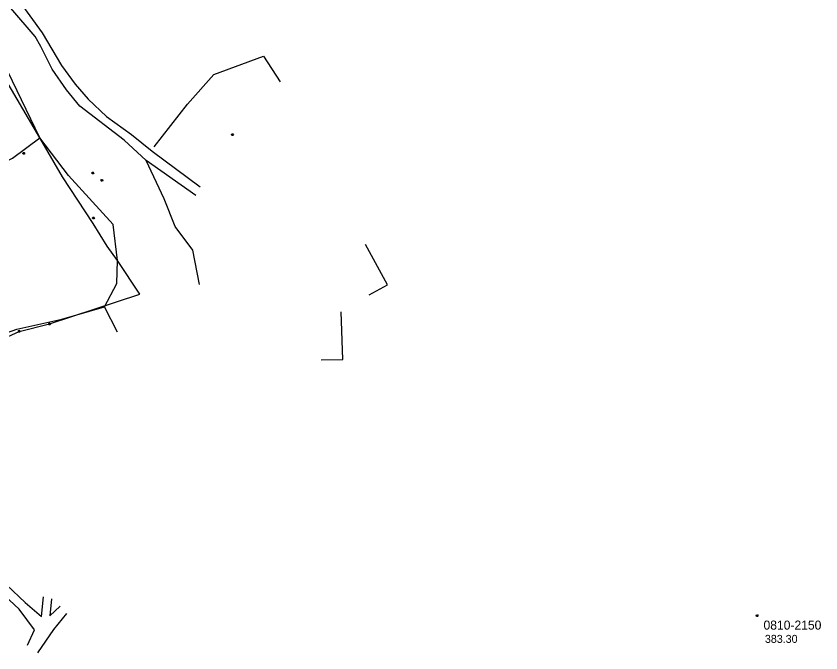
# Model space of a CAD drawing. Extents: x -664960 to -662754, y -993849 to -991145.
# Drawn here: x -663293.4 to -662991, y -993249.2 to -993009.9 of the extents above; entities that cross this region are included whole.
import ezdxf

# ---------------------------------------------------------------- set-up
doc = ezdxf.new("R2010")
doc.units = 0
for name, color, linetype in [('Vrstva 1', 7, 'Continuous'), ('Vrstva 11', 7, 'Continuous'), ('Vrstva 12', 7, 'Continuous'), ('Vrstva 13', 7, 'Continuous'), ('Vrstva 27', 7, 'Continuous'), ('Vrstva 63', 7, 'Continuous'), ('Vrstva 8', 7, 'Continuous')]:
    doc.layers.add(name, color=color, linetype=linetype)

msp = doc.modelspace()

# ---------------------------------------------------------------- linework, layer by layer
at = {"layer": 'Vrstva 11'}
for points in [[(-663160.75, -993114.59), (-663153.85, -993110.87), (-663162.09, -993095.67)], [(-663178.82, -993139.08), (-663170.63, -993138.89), (-663171.3, -993121.06)]]:
    msp.add_lwpolyline(points, dxfattribs=at)
at = {"layer": 'Vrstva 12'}
for points in [[(-663341.694, -992879.229), (-663322.507, -992871.739), (-663298.884, -992862.11), (-663264.82, -992847.459), (-663233.108, -992834.58), (-663222.646, -992831), (-663216.562, -992854.338), (-663208.65, -992879.993), (-663205.047, -992891.622), (-663214.885, -992896.327), (-663246.058, -992908.874), (-663279.261, -992922.204), (-663312.653, -992935.665), (-663315.597, -992937.424), (-663302.153, -992960.934), (-663291.183, -992979.614), (-663303.608, -992986.729), (-663300.296, -992993.203), (-663283.685, -993016.224)], [(-663279.937, -993029.881), (-663284.18, -993021.245), (-663286.251, -993017.598), (-663295.385, -993006.871), (-663302.847, -992995.239), (-663306.136, -992988.814), (-663320.354, -992965.17), (-663332.47, -992944.063), (-663341.969, -992926.051), (-663345.056, -992920.251), (-663345.368, -992917.078), (-663351.443, -992905.617), (-663355.536, -992901.623), (-663361.685, -992887.35)], [(-663241.501, -993059.037), (-663229.069, -993043.029), (-663219.099, -993031.807), (-663200.455, -993024.974), (-663194.204, -993034.639)]]:
    msp.add_lwpolyline(points, dxfattribs=at)
at = {"layer": 'Vrstva 13'}
for points in [[(-663211.953, -993054.171), (-663211.773, -993054.471), (-663211.953, -993054.771), (-663212.313, -993054.771), (-663212.493, -993054.471), (-663212.313, -993054.171), (-663211.953, -993054.171)], [(-663264.455, -993068.527), (-663264.275, -993068.827), (-663264.455, -993069.127), (-663264.815, -993069.127), (-663264.995, -993068.827), (-663264.815, -993068.527), (-663264.455, -993068.527)], [(-663260.995, -993071.332), (-663260.815, -993071.632), (-663260.995, -993071.932), (-663261.355, -993071.932), (-663261.535, -993071.632), (-663261.355, -993071.332), (-663260.995, -993071.332)], [(-663264.174, -993085.445), (-663263.994, -993085.745), (-663264.174, -993086.045), (-663264.534, -993086.045), (-663264.714, -993085.745), (-663264.534, -993085.445), (-663264.174, -993085.445)]]:
    msp.add_lwpolyline(points, dxfattribs=at)
at = {"layer": 'Vrstva 27'}
msp.add_line((-663225.899, -993077.285), (-663244.556, -993064.146), dxfattribs=at)
for points in [[(-663283.685, -993016.224), (-663276.366, -993028.5), (-663271.291, -993035.466), (-663266.312, -993041.047), (-663259.502, -993047.649), (-663250.06, -993054.421), (-663242.267, -993060.589), (-663224.292, -993074.007)], [(-663244.556, -993064.146), (-663252.811, -993056.507), (-663269.463, -993043.757), (-663274.517, -993037.639), (-663279.937, -993029.881)], [(-663375.681, -993138.823), (-663369.729, -993146.08), (-663355.79, -993162.06), (-663341.44, -993177.26), (-663326.1, -993194.37), (-663310.82, -993210.78), (-663290.07, -993230.27), (-663283.91, -993235.59), (-663283.15, -993228.16)], [(-663289.16, -993246.32), (-663286.47, -993240.57), (-663292.32, -993232.82), (-663314.09, -993212.62)], [(-663280.19, -993228.94), (-663280.79, -993235.28), (-663276.89, -993231.7)], [(-663274.46, -993234.43), (-663279.38, -993240.47), (-663285.45, -993249.22)]]:
    msp.add_lwpolyline(points, dxfattribs=at)
at = {"layer": 'Vrstva 63'}
msp.add_line((-663255.294, -993128.694), (-663260.264, -993119.089), dxfattribs=at)
for points in [[(-663246.904, -993114.369), (-663255.353, -993101.711), (-663256.984, -993088.158), (-663273.685, -993069.79), (-663284.547, -993055.601), (-663300.016, -993023.681), (-663309.766, -993014.643)], [(-663302.753, -993130.937), (-663293.129, -993127.585), (-663276.272, -993123.778), (-663260.264, -993119.089), (-663255.612, -993110.404), (-663255.353, -993101.711), (-663259.265, -993096.389), (-663264.503, -993087.851), (-663276.047, -993070.297), (-663284.547, -993055.601), (-663299.44, -993030.172)], [(-663386.718, -993110.575), (-663331.567, -993082.506), (-663294.803, -993063.252), (-663284.547, -993055.601)], [(-663290.388, -993061.124), (-663290.208, -993061.424), (-663290.388, -993061.724), (-663290.748, -993061.724), (-663290.928, -993061.424), (-663290.748, -993061.124), (-663290.388, -993061.124)], [(-663224.507, -993110.691), (-663226.991, -993097.901), (-663233.674, -993088.961), (-663237.768, -993078.531), (-663244.556, -993064.146)], [(-663311.407, -993135.342), (-663299.548, -993131.706), (-663292.235, -993128.405), (-663280.868, -993125.552), (-663246.904, -993114.369)], [(-663280.688, -993125.252), (-663280.508, -993125.552), (-663280.688, -993125.852), (-663281.048, -993125.852), (-663281.228, -993125.552), (-663281.048, -993125.252), (-663280.688, -993125.252)], [(-663292.055, -993128.105), (-663291.875, -993128.405), (-663292.055, -993128.705), (-663292.415, -993128.705), (-663292.595, -993128.405), (-663292.415, -993128.105), (-663292.055, -993128.105)]]:
    msp.add_lwpolyline(points, dxfattribs=at)
at = {"layer": 'Vrstva 8'}
msp.add_lwpolyline([(-663014.8, -993234.97), (-663014.62, -993235.27), (-663014.8, -993235.57), (-663015.16, -993235.57), (-663015.34, -993235.27), (-663015.16, -993234.97), (-663014.8, -993234.97)], dxfattribs=at)

# ---------------------------------------------------------------- texts
at = {"layer": 'Vrstva 1'}
msp.add_text('0810-2150', height=3.4, dxfattribs=at).set_placement((-663012.58, -993240.47))
at = {"layer": 'Vrstva 63'}
msp.add_text('383.30', height=3, dxfattribs=at).set_placement((-663012.056, -993245.45))

doc.saveas('drawing.dxf')
